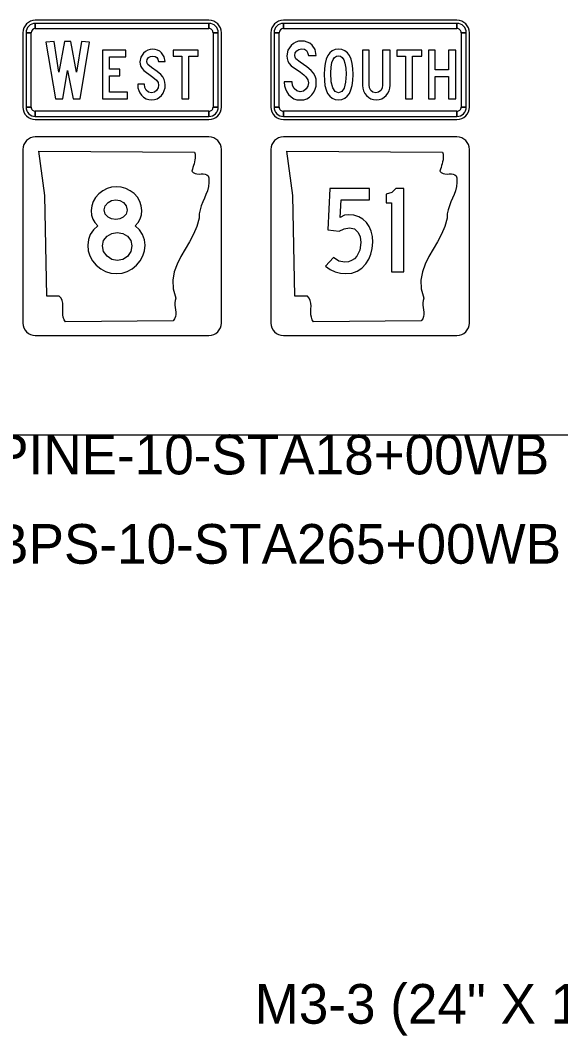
# Model space of a CAD drawing. Extents: x 1001568 to 1002149, y 1840825 to 1841423.
# Drawn here: x 1001937.13 to 1001942.57, y 1841279.41 to 1841289.64 of the extents above; entities that cross this region are included whole.
import ezdxf

# ---------------------------------------------------------------- set-up
doc = ezdxf.new("R2010")
doc.units = 0
for name, color, linetype in [('40', 7, 'Continuous'), ('R_No Plot', 7, 'Continuous'), ('SIGNS', 7, 'Continuous')]:
    doc.layers.add(name, color=color, linetype=linetype)

msp = doc.modelspace()

# ---------------------------------------------------------------- linework, layer by layer
at = {"layer": 'R_No Plot'}
msp.add_line((1001890.65, 1841285.469), (1001982.133, 1841285.469), dxfattribs=at)
at = {"layer": 'SIGNS'}
for p, q in [((1001939.029, 1841289.645), (1001937.279, 1841289.645)), ((1001937.279, 1841289.561), (1001937.279, 1841289.613)), ((1001939.029, 1841289.613), (1001939.029, 1841289.561)), ((1001941.529, 1841289.645), (1001939.779, 1841289.645)), ((1001939.779, 1841289.561), (1001939.779, 1841289.613)), ((1001941.529, 1841289.613), (1001941.529, 1841289.561)), ((1001937.154, 1841289.52), (1001937.154, 1841288.77)), ((1001937.186, 1841289.52), (1001937.238, 1841289.52)), ((1001939.071, 1841289.52), (1001939.123, 1841289.52)), ((1001939.154, 1841288.77), (1001939.154, 1841289.52)), ((1001939.654, 1841289.52), (1001939.654, 1841288.77)), ((1001939.686, 1841289.52), (1001939.738, 1841289.52)), ((1001941.571, 1841289.52), (1001941.623, 1841289.52)), ((1001941.654, 1841288.77), (1001941.654, 1841289.52)), ((1001937.238, 1841288.77), (1001937.186, 1841288.77)), ((1001937.279, 1841288.676), (1001937.279, 1841288.728)), ((1001939.029, 1841288.728), (1001939.029, 1841288.676)), ((1001939.123, 1841288.77), (1001939.071, 1841288.77)), ((1001939.738, 1841288.77), (1001939.686, 1841288.77)), ((1001939.779, 1841288.676), (1001939.779, 1841288.728)), ((1001941.529, 1841288.728), (1001941.529, 1841288.676)), ((1001941.623, 1841288.77), (1001941.571, 1841288.77)), ((1001937.279, 1841288.645), (1001939.029, 1841288.645)), ((1001939.779, 1841288.645), (1001941.529, 1841288.645)), ((1001939.029, 1841288.469), (1001937.279, 1841288.469)), ((1001941.529, 1841288.469), (1001939.779, 1841288.469)), ((1001937.154, 1841288.344), (1001937.154, 1841286.594)), ((1001939.154, 1841286.594), (1001939.154, 1841288.344)), ((1001939.654, 1841288.344), (1001939.654, 1841286.594)), ((1001941.654, 1841286.594), (1001941.654, 1841288.344)), ((1001937.154, 1841286.594), (1001937.154, 1841286.594)), ((1001939.654, 1841286.594), (1001939.654, 1841286.594)), ((1001937.279, 1841286.469), (1001939.029, 1841286.469)), ((1001939.779, 1841286.469), (1001941.529, 1841286.469))]:
    msp.add_line(p, q, dxfattribs=at)
for points in [[(1001939.029, 1841289.613), (1001937.279, 1841289.613), (1001937.279, 1841289.561), (1001939.029, 1841289.561), (1001939.029, 1841289.613), (1001939.029, 1841289.613)], [(1001941.529, 1841289.613), (1001939.779, 1841289.613), (1001939.779, 1841289.561), (1001941.529, 1841289.561), (1001941.529, 1841289.613), (1001941.529, 1841289.613)], [(1001937.186, 1841289.52), (1001937.186, 1841288.77), (1001937.238, 1841288.77), (1001937.238, 1841289.52), (1001937.186, 1841289.52), (1001937.186, 1841289.52)], [(1001939.123, 1841288.77), (1001939.123, 1841289.52), (1001939.071, 1841289.52), (1001939.071, 1841288.77), (1001939.123, 1841288.77), (1001939.123, 1841288.77)], [(1001939.686, 1841289.52), (1001939.686, 1841288.77), (1001939.738, 1841288.77), (1001939.738, 1841289.52), (1001939.686, 1841289.52), (1001939.686, 1841289.52)], [(1001941.623, 1841288.77), (1001941.623, 1841289.52), (1001941.571, 1841289.52), (1001941.571, 1841288.77), (1001941.623, 1841288.77), (1001941.623, 1841288.77)], [(1001937.482, 1841288.853), (1001937.558, 1841288.853), (1001937.605, 1841289.138), (1001937.661, 1841288.853), (1001937.732, 1841288.853), (1001937.825, 1841289.425), (1001937.744, 1841289.43), (1001937.693, 1841289.122), (1001937.638, 1841289.43), (1001937.573, 1841289.43), (1001937.516, 1841289.122), (1001937.468, 1841289.43), (1001937.386, 1841289.425)], [(1001939.788, 1841289.025), (1001939.788, 1841289.02), (1001939.79, 1841288.985), (1001939.799, 1841288.953), (1001939.813, 1841288.923), (1001939.832, 1841288.896), (1001939.857, 1841288.872), (1001939.885, 1841288.855), (1001939.916, 1841288.845), (1001939.95, 1841288.842), (1001939.984, 1841288.845), (1001940.015, 1841288.855), (1001940.043, 1841288.871), (1001940.067, 1841288.894), (1001940.086, 1841288.921), (1001940.1, 1841288.95), (1001940.108, 1841288.982), (1001940.111, 1841289.017), (1001940.108, 1841289.05), (1001940.098, 1841289.081), (1001940.082, 1841289.111), (1001940.06, 1841289.139), (1001940.017, 1841289.176), (1001939.95, 1841289.222), (1001939.906, 1841289.255), (1001939.897, 1841289.272), (1001939.894, 1841289.291), (1001939.899, 1841289.316), (1001939.914, 1841289.338), (1001939.936, 1841289.352), (1001939.963, 1841289.357), (1001939.991, 1841289.353), (1001940.012, 1841289.339), (1001940.023, 1841289.319), (1001940.032, 1841289.291), (1001940.111, 1841289.291), (1001940.098, 1841289.349), (1001940.068, 1841289.395), (1001940.046, 1841289.413), (1001940.02, 1841289.426), (1001939.992, 1841289.434), (1001939.961, 1841289.436), (1001939.931, 1841289.434), (1001939.905, 1841289.425), (1001939.88, 1841289.411), (1001939.857, 1841289.392), (1001939.825, 1841289.344), (1001939.814, 1841289.288), (1001939.817, 1841289.26), (1001939.825, 1841289.233), (1001939.838, 1841289.209), (1001939.858, 1841289.187), (1001939.951, 1841289.121), (1001939.985, 1841289.094), (1001940.007, 1841289.075), (1001940.026, 1841289.046), (1001940.032, 1841289.016), (1001940.026, 1841288.982), (1001940.01, 1841288.953), (1001939.983, 1841288.932), (1001939.95, 1841288.925), (1001939.915, 1841288.933), (1001939.888, 1841288.956), (1001939.872, 1841288.988), (1001939.867, 1841289.025)], [(1001938.209, 1841288.92), (1001938.028, 1841288.92), (1001938.028, 1841289.084), (1001938.131, 1841289.084), (1001938.131, 1841289.151), (1001938.028, 1841289.151), (1001938.028, 1841289.276), (1001938.19, 1841289.276), (1001938.19, 1841289.343), (1001937.957, 1841289.343), (1001937.957, 1841288.853), (1001938.209, 1841288.853)], [(1001938.312, 1841289), (1001938.312, 1841288.996), (1001938.314, 1841288.966), (1001938.321, 1841288.938), (1001938.333, 1841288.913), (1001938.35, 1841288.89), (1001938.371, 1841288.869), (1001938.395, 1841288.855), (1001938.422, 1841288.846), (1001938.451, 1841288.843), (1001938.48, 1841288.846), (1001938.507, 1841288.855), (1001938.53, 1841288.869), (1001938.551, 1841288.888), (1001938.568, 1841288.911), (1001938.579, 1841288.936), (1001938.587, 1841288.963), (1001938.589, 1841288.993), (1001938.586, 1841289.022), (1001938.578, 1841289.049), (1001938.564, 1841289.074), (1001938.545, 1841289.098), (1001938.508, 1841289.13), (1001938.451, 1841289.169), (1001938.413, 1841289.198), (1001938.405, 1841289.212), (1001938.402, 1841289.228), (1001938.407, 1841289.25), (1001938.42, 1841289.269), (1001938.439, 1841289.281), (1001938.462, 1841289.285), (1001938.486, 1841289.281), (1001938.504, 1841289.27), (1001938.513, 1841289.253), (1001938.521, 1841289.228), (1001938.589, 1841289.228), (1001938.578, 1841289.278), (1001938.552, 1841289.318), (1001938.533, 1841289.333), (1001938.511, 1841289.344), (1001938.487, 1841289.351), (1001938.46, 1841289.353), (1001938.435, 1841289.351), (1001938.412, 1841289.344), (1001938.391, 1841289.332), (1001938.371, 1841289.315), (1001938.343, 1841289.274), (1001938.334, 1841289.226), (1001938.337, 1841289.202), (1001938.344, 1841289.179), (1001938.355, 1841289.158), (1001938.372, 1841289.139), (1001938.451, 1841289.082), (1001938.481, 1841289.06), (1001938.499, 1841289.043), (1001938.516, 1841289.019), (1001938.521, 1841288.992), (1001938.516, 1841288.963), (1001938.502, 1841288.939), (1001938.479, 1841288.921), (1001938.451, 1841288.915), (1001938.421, 1841288.921), (1001938.397, 1841288.942), (1001938.384, 1841288.968), (1001938.38, 1841289)], [(1001938.757, 1841288.853), (1001938.828, 1841288.853), (1001938.828, 1841289.282), (1001938.92, 1841289.282), (1001938.92, 1841289.343), (1001938.667, 1841289.343), (1001938.667, 1841289.282), (1001938.757, 1841289.282)], [(1001940.577, 1841289.343), (1001940.577, 1841288.988), (1001940.58, 1841288.96), (1001940.587, 1841288.933), (1001940.6, 1841288.908), (1001940.618, 1841288.886), (1001940.639, 1841288.867), (1001940.662, 1841288.854), (1001940.689, 1841288.846), (1001940.717, 1841288.843), (1001940.745, 1841288.846), (1001940.771, 1841288.855), (1001940.794, 1841288.869), (1001940.815, 1841288.888), (1001940.832, 1841288.911), (1001940.844, 1841288.935), (1001940.851, 1841288.962), (1001940.854, 1841288.99), (1001940.854, 1841289.343), (1001940.779, 1841289.343), (1001940.779, 1841288.993), (1001940.774, 1841288.962), (1001940.761, 1841288.938), (1001940.739, 1841288.92), (1001940.71, 1841288.914), (1001940.682, 1841288.92), (1001940.661, 1841288.939), (1001940.648, 1841288.963), (1001940.644, 1841288.993), (1001940.644, 1841289.343)], [(1001941.011, 1841288.853), (1001941.082, 1841288.853), (1001941.082, 1841289.282), (1001941.173, 1841289.282), (1001941.173, 1841289.343), (1001940.921, 1841289.343), (1001940.921, 1841289.282), (1001941.011, 1841289.282)], [(1001941.241, 1841288.853), (1001941.308, 1841288.853), (1001941.308, 1841289.078), (1001941.443, 1841289.078), (1001941.443, 1841288.853), (1001941.518, 1841288.853), (1001941.518, 1841289.343), (1001941.443, 1841289.343), (1001941.443, 1841289.147), (1001941.308, 1841289.147), (1001941.308, 1841289.343), (1001941.241, 1841289.343)], [(1001937.279, 1841288.676), (1001939.029, 1841288.676), (1001939.029, 1841288.728), (1001937.279, 1841288.728), (1001937.279, 1841288.676), (1001937.279, 1841288.676)], [(1001939.779, 1841288.676), (1001941.529, 1841288.676), (1001941.529, 1841288.728), (1001939.779, 1841288.728), (1001939.779, 1841288.676), (1001939.779, 1841288.676)], [(1001938.884, 1841288.315), (1001938.889, 1841288.296), (1001938.891, 1841288.276), (1001938.89, 1841288.257), (1001938.888, 1841288.238), (1001938.884, 1841288.219), (1001938.879, 1841288.2), (1001938.873, 1841288.181), (1001938.868, 1841288.163), (1001938.862, 1841288.144), (1001938.857, 1841288.126), (1001938.871, 1841288.11), (1001938.889, 1841288.101), (1001938.908, 1841288.097), (1001938.93, 1841288.096), (1001938.951, 1841288.097), (1001938.972, 1841288.097), (1001938.991, 1841288.095), (1001939.008, 1841288.089), (1001939.021, 1841288.077), (1001939.029, 1841288.057), (1001939.029, 1841288.011), (1001939.024, 1841287.969), (1001939.013, 1841287.928), (1001938.999, 1841287.89), (1001938.983, 1841287.851), (1001938.967, 1841287.814), (1001938.952, 1841287.775), (1001938.94, 1841287.735), (1001938.931, 1841287.694), (1001938.929, 1841287.65), (1001938.907, 1841287.568), (1001938.874, 1841287.489), (1001938.833, 1841287.414), (1001938.789, 1841287.339), (1001938.746, 1841287.264), (1001938.708, 1841287.188), (1001938.68, 1841287.11), (1001938.665, 1841287.027), (1001938.669, 1841286.94), (1001938.694, 1841286.846), (1001938.687, 1841286.823), (1001938.684, 1841286.799), (1001938.685, 1841286.775), (1001938.688, 1841286.751), (1001938.691, 1841286.727), (1001938.694, 1841286.704), (1001938.694, 1841286.681), (1001938.691, 1841286.659), (1001938.683, 1841286.638), (1001938.667, 1841286.618), (1001937.584, 1841286.608), (1001937.569, 1841286.628), (1001937.561, 1841286.652), (1001937.557, 1841286.678), (1001937.557, 1841286.706), (1001937.557, 1841286.736), (1001937.558, 1841286.765), (1001937.556, 1841286.794), (1001937.55, 1841286.821), (1001937.539, 1841286.846), (1001937.521, 1841286.866), (1001937.394, 1841286.866), (1001937.376, 1841287.878), (1001937.313, 1841288.325), (1001938.884, 1841288.315), (1001938.884, 1841288.315)], [(1001941.384, 1841288.315), (1001941.389, 1841288.296), (1001941.391, 1841288.276), (1001941.39, 1841288.257), (1001941.388, 1841288.238), (1001941.384, 1841288.219), (1001941.379, 1841288.2), (1001941.373, 1841288.181), (1001941.368, 1841288.163), (1001941.362, 1841288.144), (1001941.357, 1841288.126), (1001941.371, 1841288.11), (1001941.389, 1841288.101), (1001941.408, 1841288.097), (1001941.43, 1841288.096), (1001941.451, 1841288.097), (1001941.472, 1841288.097), (1001941.491, 1841288.095), (1001941.508, 1841288.089), (1001941.521, 1841288.077), (1001941.529, 1841288.057), (1001941.529, 1841288.011), (1001941.524, 1841287.969), (1001941.513, 1841287.928), (1001941.499, 1841287.89), (1001941.483, 1841287.851), (1001941.467, 1841287.814), (1001941.452, 1841287.775), (1001941.44, 1841287.735), (1001941.431, 1841287.694), (1001941.429, 1841287.65), (1001941.407, 1841287.568), (1001941.374, 1841287.489), (1001941.333, 1841287.414), (1001941.289, 1841287.339), (1001941.246, 1841287.264), (1001941.208, 1841287.188), (1001941.18, 1841287.11), (1001941.165, 1841287.027), (1001941.169, 1841286.94), (1001941.194, 1841286.846), (1001941.187, 1841286.823), (1001941.184, 1841286.799), (1001941.185, 1841286.775), (1001941.188, 1841286.751), (1001941.191, 1841286.727), (1001941.194, 1841286.704), (1001941.194, 1841286.681), (1001941.191, 1841286.659), (1001941.183, 1841286.638), (1001941.167, 1841286.618), (1001940.084, 1841286.608), (1001940.069, 1841286.628), (1001940.061, 1841286.652), (1001940.057, 1841286.678), (1001940.057, 1841286.706), (1001940.057, 1841286.736), (1001940.058, 1841286.765), (1001940.056, 1841286.794), (1001940.05, 1841286.821), (1001940.039, 1841286.846), (1001940.021, 1841286.866), (1001939.894, 1841286.866), (1001939.876, 1841287.878), (1001939.813, 1841288.325), (1001941.384, 1841288.315), (1001941.384, 1841288.315)], [(1001940.205, 1841287.167), (1001940.252, 1841287.134), (1001940.302, 1841287.111), (1001940.354, 1841287.097), (1001940.409, 1841287.092), (1001940.468, 1841287.098), (1001940.522, 1841287.116), (1001940.569, 1841287.147), (1001940.61, 1841287.19), (1001940.64, 1841287.237), (1001940.662, 1841287.29), (1001940.675, 1841287.347), (1001940.68, 1841287.41), (1001940.676, 1841287.468), (1001940.664, 1841287.52), (1001940.645, 1841287.566), (1001940.618, 1841287.607), (1001940.581, 1841287.641), (1001940.539, 1841287.666), (1001940.49, 1841287.681), (1001940.435, 1841287.686), (1001940.394, 1841287.68), (1001940.351, 1841287.659), (1001940.36, 1841287.835), (1001940.647, 1841287.835), (1001940.647, 1841287.95), (1001940.246, 1841287.95), (1001940.226, 1841287.534), (1001940.342, 1841287.519), (1001940.391, 1841287.545), (1001940.444, 1841287.554), (1001940.496, 1841287.542), (1001940.534, 1841287.508), (1001940.554, 1841287.462), (1001940.56, 1841287.405), (1001940.55, 1841287.33), (1001940.52, 1841287.269), (1001940.496, 1841287.242), (1001940.467, 1841287.223), (1001940.434, 1841287.211), (1001940.397, 1841287.208), (1001940.339, 1841287.219), (1001940.285, 1841287.255)], [(1001940.869, 1841287.109), (1001940.992, 1841287.109), (1001940.992, 1841287.95), (1001940.911, 1841287.95), (1001940.873, 1841287.909), (1001940.814, 1841287.894), (1001940.814, 1841287.806), (1001940.869, 1841287.806)]]:
    msp.add_lwpolyline(points, close=True, dxfattribs=at)
for points in [[(1001940.481, 1841289.099), (1001940.479, 1841289.158), (1001940.472, 1841289.21), (1001940.461, 1841289.254), (1001940.445, 1841289.289), (1001940.424, 1841289.317), (1001940.4, 1841289.337), (1001940.37, 1841289.349), (1001940.336, 1841289.353), (1001940.302, 1841289.349), (1001940.272, 1841289.337), (1001940.247, 1841289.317), (1001940.226, 1841289.289), (1001940.21, 1841289.254), (1001940.199, 1841289.21), (1001940.192, 1841289.158), (1001940.19, 1841289.099), (1001940.192, 1841289.039), (1001940.198, 1841288.987), (1001940.21, 1841288.943), (1001940.225, 1841288.907), (1001940.246, 1841288.879), (1001940.27, 1841288.859), (1001940.3, 1841288.847), (1001940.333, 1841288.843), (1001940.368, 1841288.847), (1001940.398, 1841288.859), (1001940.423, 1841288.879), (1001940.444, 1841288.907), (1001940.46, 1841288.943), (1001940.472, 1841288.987), (1001940.479, 1841289.039), (1001940.481, 1841289.099)], [(1001940.411, 1841289.101), (1001940.406, 1841289.02), (1001940.391, 1841288.961), (1001940.368, 1841288.926), (1001940.334, 1841288.915), (1001940.3, 1841288.927), (1001940.276, 1841288.964), (1001940.262, 1841289.026), (1001940.257, 1841289.114), (1001940.26, 1841289.171), (1001940.269, 1841289.219), (1001940.28, 1841289.249), (1001940.295, 1841289.27), (1001940.313, 1841289.283), (1001940.334, 1841289.287), (1001940.355, 1841289.283), (1001940.373, 1841289.269), (1001940.388, 1841289.245), (1001940.399, 1841289.213), (1001940.408, 1841289.162), (1001940.411, 1841289.101)], [(1001937.279, 1841288.469), (1001937.279, 1841288.469)], [(1001939.029, 1841288.469), (1001939.029, 1841288.469)], [(1001939.779, 1841288.469), (1001939.779, 1841288.469)], [(1001941.529, 1841288.469), (1001941.529, 1841288.469)], [(1001937.154, 1841288.344), (1001937.154, 1841288.344)], [(1001939.654, 1841288.344), (1001939.654, 1841288.344)], [(1001938.287, 1841287.574), (1001938.316, 1841287.608), (1001938.336, 1841287.644), (1001938.348, 1841287.684), (1001938.353, 1841287.728), (1001938.347, 1841287.775), (1001938.333, 1841287.82), (1001938.308, 1841287.861), (1001938.274, 1841287.898), (1001938.234, 1841287.928), (1001938.192, 1841287.95), (1001938.146, 1841287.963), (1001938.097, 1841287.967), (1001938.048, 1841287.962), (1001938.003, 1841287.949), (1001937.96, 1841287.927), (1001937.92, 1841287.897), (1001937.886, 1841287.86), (1001937.862, 1841287.819), (1001937.848, 1841287.775), (1001937.843, 1841287.728), (1001937.847, 1841287.682), (1001937.859, 1841287.642), (1001937.879, 1841287.606), (1001937.908, 1841287.574), (1001937.864, 1841287.534), (1001937.833, 1841287.488), (1001937.814, 1841287.437), (1001937.808, 1841287.379), (1001937.813, 1841287.323), (1001937.829, 1841287.271), (1001937.856, 1841287.222), (1001937.894, 1841287.178), (1001937.939, 1841287.14), (1001937.988, 1841287.113), (1001938.04, 1841287.097), (1001938.097, 1841287.092), (1001938.153, 1841287.097), (1001938.206, 1841287.113), (1001938.254, 1841287.14), (1001938.299, 1841287.178), (1001938.336, 1841287.222), (1001938.363, 1841287.271), (1001938.379, 1841287.323), (1001938.385, 1841287.379), (1001938.379, 1841287.434), (1001938.36, 1841287.486), (1001938.33, 1841287.532), (1001938.287, 1841287.574)], [(1001938.204, 1841287.731), (1001938.194, 1841287.692), (1001938.166, 1841287.661), (1001938.13, 1841287.643), (1001938.09, 1841287.637), (1001938.048, 1841287.643), (1001938.012, 1841287.661), (1001937.982, 1841287.693), (1001937.973, 1841287.734), (1001937.982, 1841287.775), (1001938.012, 1841287.809), (1001938.048, 1841287.828), (1001938.09, 1841287.835), (1001938.132, 1841287.828), (1001938.168, 1841287.808), (1001938.195, 1841287.774), (1001938.204, 1841287.731)], [(1001938.253, 1841287.371), (1001938.242, 1841287.314), (1001938.208, 1841287.266), (1001938.16, 1841287.235), (1001938.105, 1841287.224), (1001938.051, 1841287.235), (1001938.003, 1841287.267), (1001937.968, 1841287.314), (1001937.956, 1841287.371), (1001937.968, 1841287.425), (1001938.003, 1841287.469), (1001938.05, 1841287.496), (1001938.105, 1841287.505), (1001938.16, 1841287.496), (1001938.207, 1841287.469), (1001938.242, 1841287.425), (1001938.253, 1841287.371)], [(1001937.279, 1841286.469), (1001937.279, 1841286.469)], [(1001939.029, 1841286.469), (1001939.029, 1841286.469)], [(1001939.779, 1841286.469), (1001939.779, 1841286.469)], [(1001941.529, 1841286.469), (1001941.529, 1841286.469)]]:
    msp.add_lwpolyline(points, dxfattribs=at)
for centre, radius, start, end in [((1001937.279, 1841289.52), 0.125, 90.0002, 179.9998), ((1001937.279, 1841289.52), 0.0937, 90.0002, 179.9998), ((1001939.029, 1841289.52), 0.125, 360, 90.0002), ((1001939.029, 1841289.52), 0.0937, 360, 90.0002), ((1001939.779, 1841289.52), 0.125, 90.0002, 179.9998), ((1001939.779, 1841289.52), 0.0937, 90.0002, 179.9998), ((1001941.529, 1841289.52), 0.125, 360, 90.0002), ((1001941.529, 1841289.52), 0.0937, 360, 90.0002), ((1001937.279, 1841289.52), 0.0417, 90.0002, 179.9998), ((1001939.029, 1841289.52), 0.0417, 360, 90.0002), ((1001939.779, 1841289.52), 0.0417, 90.0002, 179.9998), ((1001941.529, 1841289.52), 0.0417, 360, 90.0002), ((1001937.279, 1841288.77), 0.125, 179.9998, 270.0001), ((1001937.279, 1841288.77), 0.0937, 179.9998, 270.0001), ((1001937.279, 1841288.77), 0.0417, 179.9998, 270.0001), ((1001939.029, 1841288.77), 0.125, 270.0001, 0.0003), ((1001939.029, 1841288.77), 0.0937, 270.0001, 0.0003), ((1001939.029, 1841288.77), 0.0417, 270.0001, 0.0003), ((1001939.779, 1841288.77), 0.125, 179.9998, 270.0001), ((1001939.779, 1841288.77), 0.0937, 179.9998, 270.0001), ((1001939.779, 1841288.77), 0.0417, 179.9998, 270.0001), ((1001941.529, 1841288.77), 0.125, 270.0001, 0.0003), ((1001941.529, 1841288.77), 0.0937, 270.0001, 0.0003), ((1001941.529, 1841288.77), 0.0417, 270.0001, 0.0003), ((1001937.279, 1841288.344), 0.125, 90.0002, 179.9998), ((1001939.029, 1841288.344), 0.125, 360, 90), ((1001939.779, 1841288.344), 0.125, 90.0002, 179.9998), ((1001941.529, 1841288.344), 0.125, 360, 90), ((1001937.279, 1841286.594), 0.125, 180, 270), ((1001939.029, 1841286.594), 0.125, 270.0001, 0.0003), ((1001939.779, 1841286.594), 0.125, 180, 270), ((1001941.529, 1841286.594), 0.125, 270.0001, 0.0003)]:
    msp.add_arc(centre, radius, start, end, dxfattribs=at)

# ---------------------------------------------------------------- texts
at = {"layer": '40'}
for s, p in [('SS-PINE-10-STA18+00WB', (1001935.963, 1841285.069)), ('SS-BPS-10-STA265+00WB', (1001935.963, 1841284.169)), ('M3-3 (24" X 12")', (1001939.489, 1841279.534))]:
    msp.add_text(s, height=0.4, rotation=0, dxfattribs=at).set_placement(p)

doc.saveas('drawing.dxf')
